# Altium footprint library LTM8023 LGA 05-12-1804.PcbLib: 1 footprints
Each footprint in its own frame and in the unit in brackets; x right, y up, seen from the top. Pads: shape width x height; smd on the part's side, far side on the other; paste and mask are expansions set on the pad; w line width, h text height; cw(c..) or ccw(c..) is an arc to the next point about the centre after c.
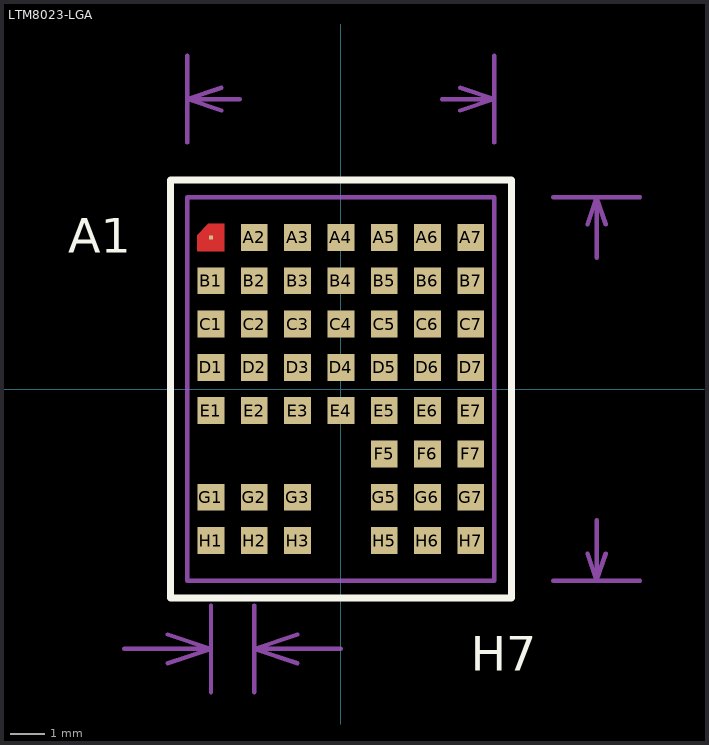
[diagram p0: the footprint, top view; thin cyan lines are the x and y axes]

## LTM8023-LGA [mil]
pads (50):
  rect 5x5 smd paste-3.5 mask-3: A1(-150,175)
  rect 31x31 smd paste-3.5 mask-3: A2(-100,175) A3(-50,175) A4(0,175) A5(50,175) A6(100,175) A7(150,175) B1(-150,125) B2(-100,125) B3(-50,125) B4(0,125) B5(50,125) B6(100,125) B7(150,125) C1(-150,75) C2(-100,75) C3(-50,75) C4(0,75) C5(50,75) C6(100,75) C7(150,75) D1(-150,25) D2(-100,25) D3(-50,25) D4(0,25) D5(50,25) D6(100,25) D7(150,25) E1(-150,-25) E2(-100,-25) E3(-50,-25) E4(0,-25) E5(50,-25) E6(100,-25) E7(150,-25) F5(50,-75) F6(100,-75) F7(150,-75) G1(-150,-125) G2(-100,-125) G3(-50,-125) G5(50,-125) G6(100,-125) G7(150,-125) H1(-150,-175) H2(-100,-175) H3(-50,-175) H5(50,-175) H6(100,-175) H7(150,-175)
TopLayer:
  region: -165.5,159.5 -134.5,159.5 -134.5,190.5 -152.5,190.5 -165.5,177.5
  lines w0.39: -165.5,159.5 -134.5,159.5 -134.5,190.5 -152.5,190.5 -165.5,177.5 -165.5,159.5
TopOverlay:
  lines w8: -196.85,-241.14 -196.85,241.14 196.85,241.14 196.85,-241.14 -196.85,-241.14
  text "H7" at 150,-325 h40
  text "A1" at -314.96,157.48 h40
Mechanical16:
  lines w5: -250,-300 -150,-300 ; -200,-316.67 -150,-300 ; -200,-283.33 -150,-300 ; -177.17,284.65 -177.17,384.65 ; -150,-350 -150,-250 ; -137.8,321.52 -177.17,334.65 ; -137.8,347.77 -177.17,334.65 ; -116.67,334.65 -177.17,334.65 ; -100,-350 -100,-250 ; -50,-316.67 -100,-300 ; -50,-283.33 -100,-300 ; 0,-300 -100,-300 ; 116.67,334.65 177.17,334.65 ; 137.8,321.52 177.17,334.65 ; 137.8,347.77 177.17,334.65 ; 177.17,284.65 177.17,384.65 ; 245.28,-221.46 345.28,-221.46 ; 245.28,221.46 345.28,221.46 ; 284.78,-189.96 295.28,-221.46 ; 284.78,189.96 295.28,221.46 ; 295.28,-151.44 295.28,-221.46 ; 295.28,151.44 295.28,221.46 ; 305.77,-189.96 295.28,-221.46 ; 305.77,189.96 295.28,221.46 ; -177.17,-221.46 177.17,-221.46 177.17,221.46 -177.17,221.46 -177.17,-221.46
  text "11.25 (mm)" at 316.02,-141.44 h31.5
  text "9 (mm)" at -106.67,309.97 h39.37
  text "1.27 (mm)" at -325.77,-419.97 h50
